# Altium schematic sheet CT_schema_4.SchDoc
size 422 x 246 mm
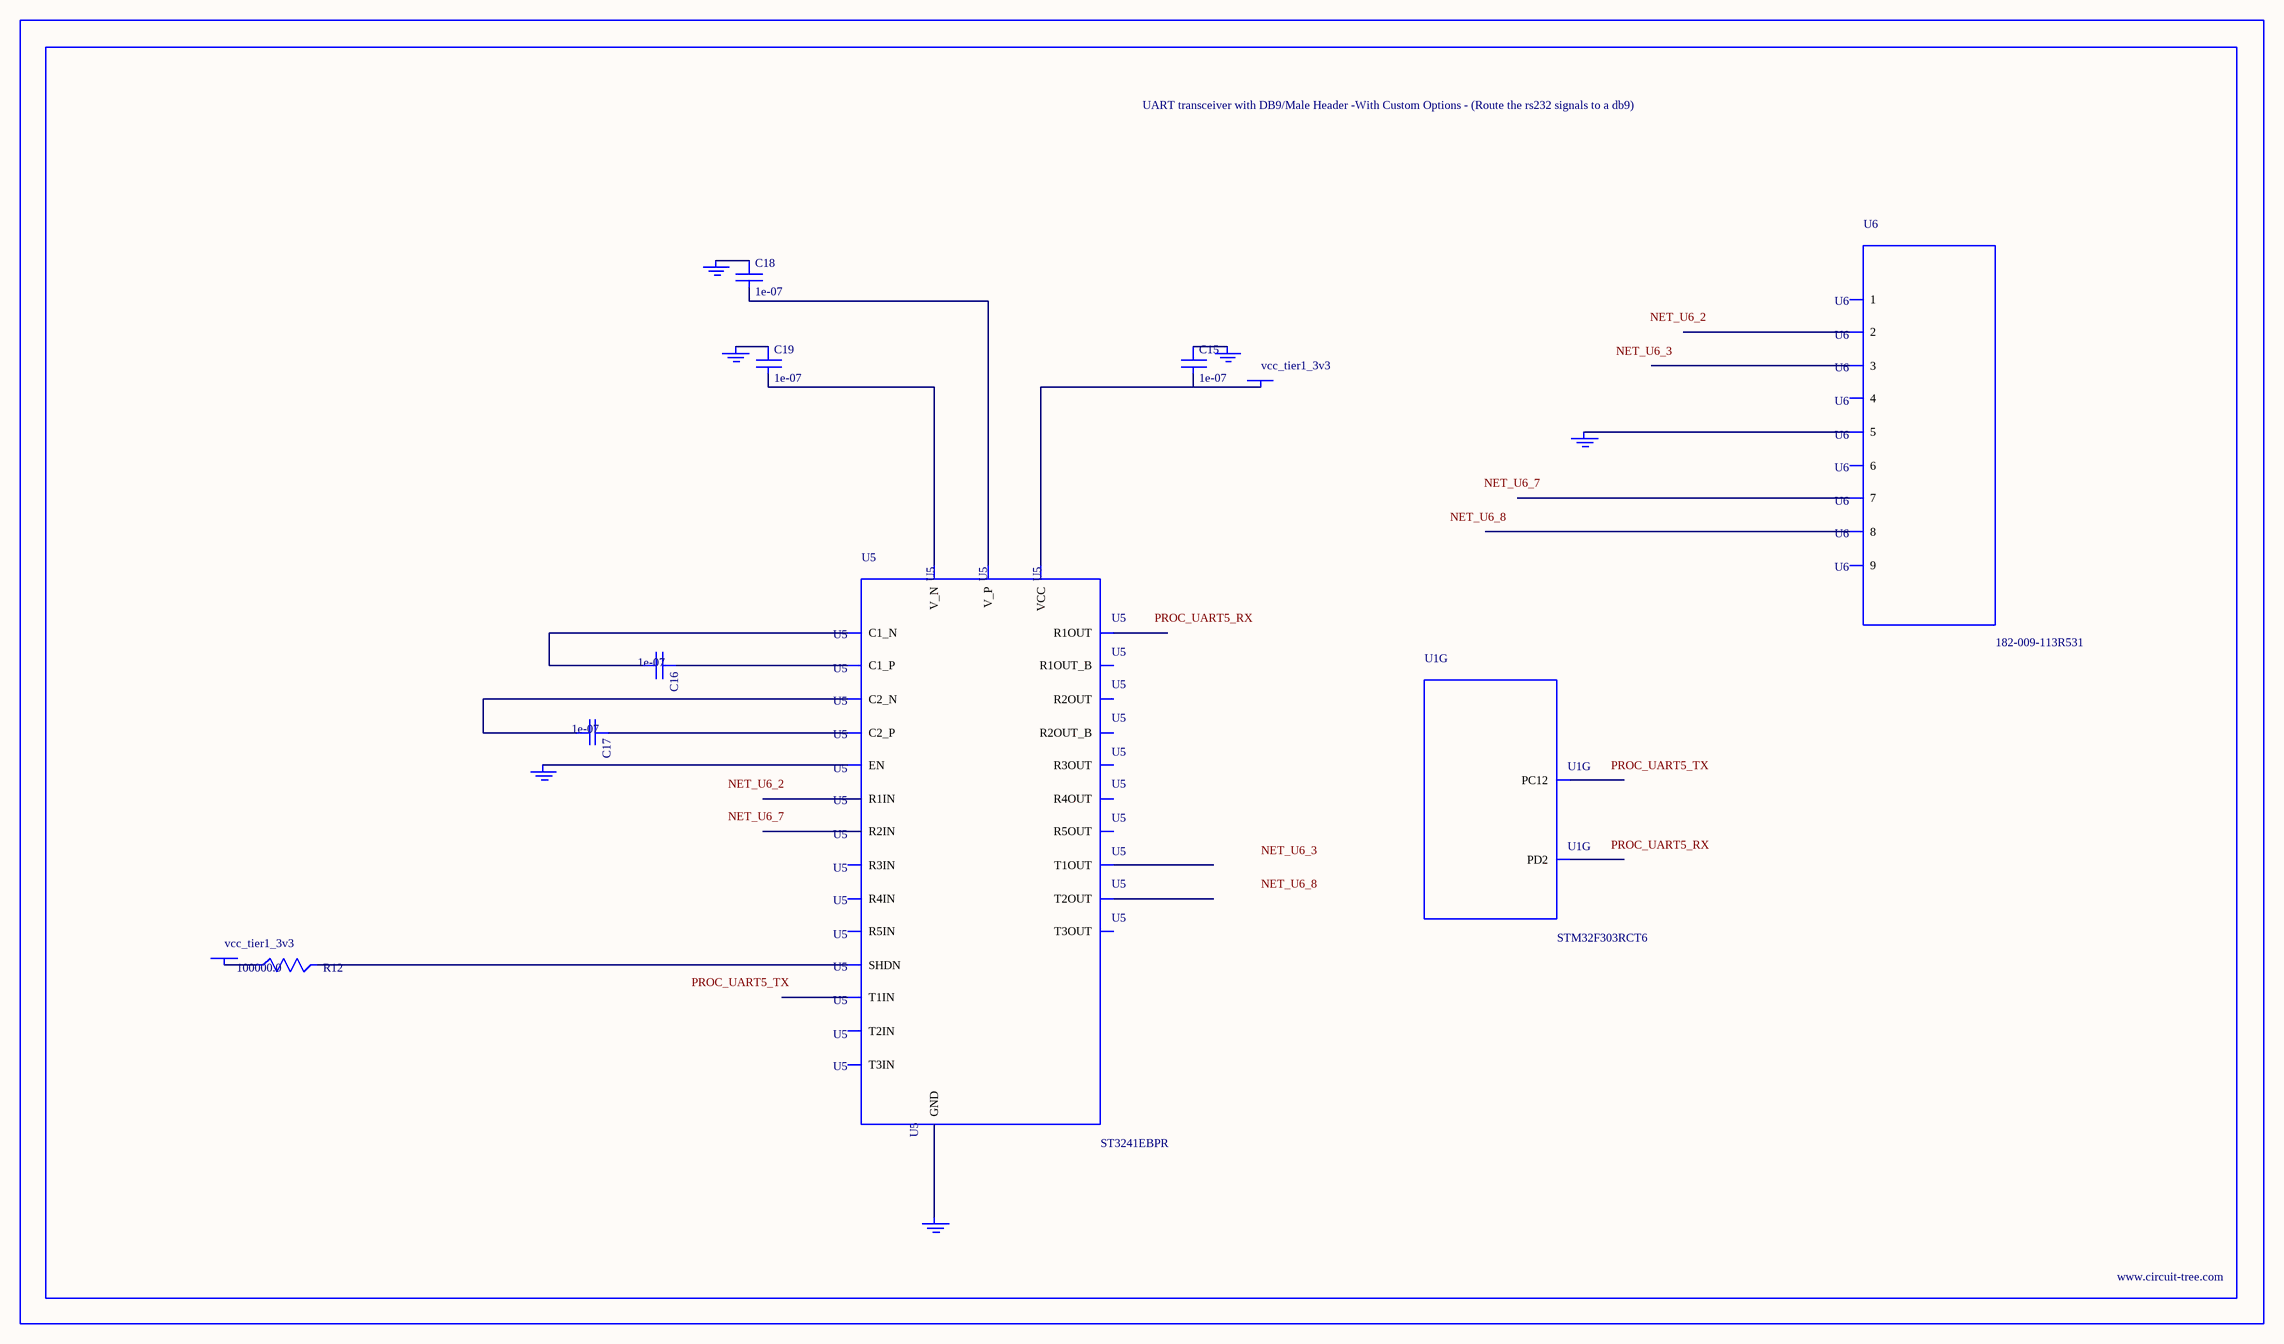
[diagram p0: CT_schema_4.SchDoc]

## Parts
BORDER3  (no value)
C15  1e-07  [C0402]
C16  1e-07  [C0402]
C17  1e-07  [C0402]
C18  1e-07  [C0402]
C19  1e-07  [C0402]
GND_INSTANCE_3_0  (no value)
GND_INSTANCE_3_1  (no value)
GND_INSTANCE_3_2  (no value)
GND_INSTANCE_3_3  (no value)
GND_INSTANCE_3_4  (no value)
GND_INSTANCE_3_5  (no value)
POWER_INSTANCE_3_0  vcc_tier1_3v3
POWER_INSTANCE_3_1  vcc_tier1_3v3
R12  100000.0  [R0603]
U1  STM32F303RCT6  [LQFP64]  (part G of 9)
U5  ST3241EBPR  [SSOP-28]
U6  182-009-113R531  [182-009-MALE]

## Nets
NetC15_1: C15.1 GND_INSTANCE_3_2.0(GND)
NetC15_2: C15.2 POWER_INSTANCE_3_1.0(PWR) U5.26(VCC)
NetC16_1: C16.1 U5.28(C1_P)
NetC16_2: C16.2 U5.24(C1_N)
NetC17_1: C17.1 U5.1(C2_P)
NetC17_2: C17.2 U5.2(C2_N)
NetC18_1: C18.1 GND_INSTANCE_3_3.0(GND)
NetC18_2: C18.2 U5.27(V_P)
NetC19_1: C19.1 GND_INSTANCE_3_0.0(GND)
NetC19_2: C19.2 U5.3(V_N)
NetGND_INSTANCE_3_1_0: GND_INSTANCE_3_1.0(GND) U5.23(EN)
NetGND_INSTANCE_3_4_0: GND_INSTANCE_3_4.0(GND) U5.25(GND)
NetGND_INSTANCE_3_5_0: GND_INSTANCE_3_5.0(GND) U6.5
NetPOWER_INSTANCE_3_0_0: POWER_INSTANCE_3_0.0(PWR) R12.1
NetR12_2: R12.2 U5.22(SHDN)

Not connected (* = marked no-connect by the designer): U1 53(PC12) 54(PD2); U5 4(R1IN) 5(R2IN) 6(R3IN) 7(R4IN) 8(R5IN) 9(T1OUT) 10(T2OUT) 11(T3OUT) 12(T3IN) 13(T2IN) 14(T1IN) 15(R5OUT) 16(R4OUT) 17(R3OUT) 18(R2OUT) 19(R1OUT) 20(R2OUT_B) 21(R1OUT_B); U6 1 2 3 4 6 7 8 9

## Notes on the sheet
- Labels drawn without touching a wire or pin: NET_U6_2, NET_U6_3, NET_U6_7, NET_U6_8, PROC_UART5_RX, PROC_UART5_TX

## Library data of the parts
BORDER3 = BORDER_PAGE3
C15-C19 = C0402C104K3RACTU
GND_INSTANCE_3_0-GND_INSTANCE_3_5 = GND
POWER_INSTANCE_3_0 POWER_INSTANCE_3_1 = PWR
R12 = RC0603JR-07100KL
